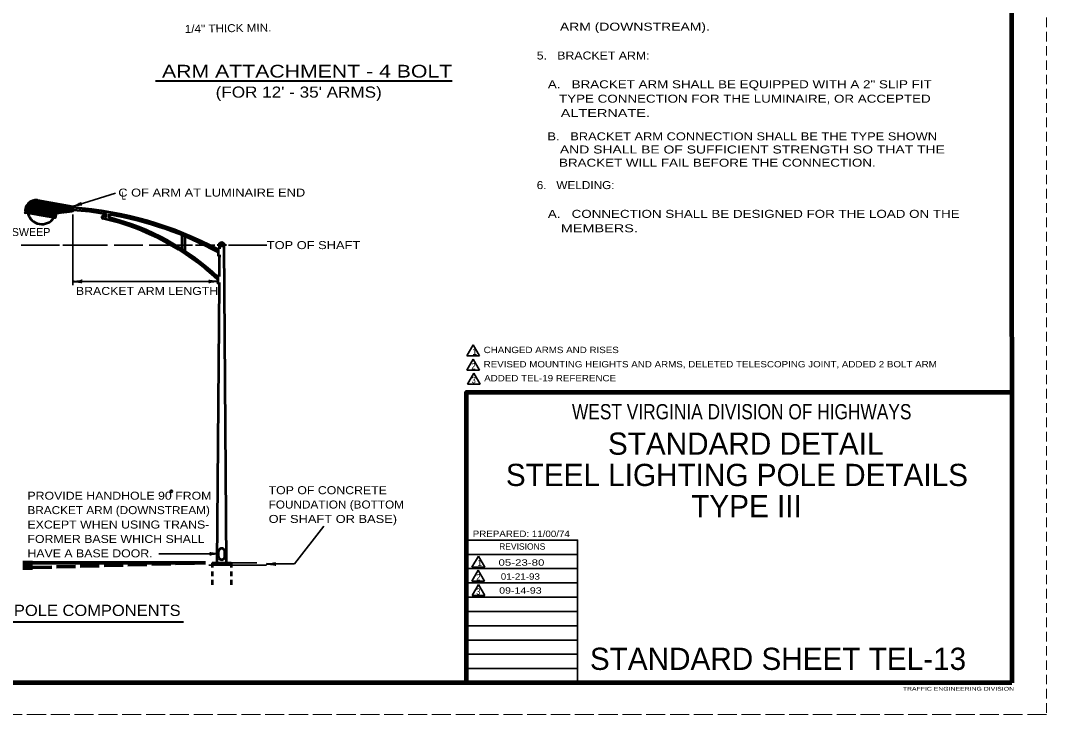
# Model space of a CAD drawing. Extents: x -1 to 679, y -228 to 440.
# Drawn here: x 356 to 679, y 0.2 to 218.8 of the extents above; entities that cross this region are included whole.
import ezdxf
from ezdxf.enums import TextEntityAlignment as Align

# ---------------------------------------------------------------- set-up
doc = ezdxf.new("R2010")
doc.units = 0
doc.header["$PDMODE"] = 32
doc.header["$PDSIZE"] = 0.5
for name, pattern in [('LONG_DASHED', [7.5, 6, -1.5]), ('MEDIUM_DASHED', [4.5, 3, -1.5]), ('SHORT_DASHED', [2.7, 1.5, -1.2])]:
    doc.linetypes.add(name, pattern=pattern)
doc.layers.add('1', color=7, linetype='Continuous', lineweight=35)
doc.layers.add('61', color=7, linetype='Continuous', lineweight=35)

msp = doc.modelspace()

# ---------------------------------------------------------------- linework, layer by layer
at = {"layer": '1', "linetype": 'MEDIUM_DASHED', "lineweight": 13}
msp.add_line((679.041, 440.237), (679.021, 0.217), dxfattribs=at)
at = {"layer": '1', "lineweight": 40}
for p, q in [((398.499, 199.759), (491.884, 199.759)), ((352.69, 29.414), (407.27, 29.414))]:
    msp.add_line(p, q, dxfattribs=at)
at = {"layer": '1', "lineweight": 53}
for p, q in [((357.57, 159.554), (360.171, 162.134)), ((357.611, 159.674), (360.03, 162.094)), ((357.671, 159.834), (359.87, 162.054)), ((357.71, 159.994), (359.71, 161.994)), ((357.791, 160.194), (359.53, 161.914)), ((357.89, 160.394), (359.31, 161.814)), ((358.05, 160.654), (359.05, 161.654)), ((358.09, 159.954), (360.31, 162.154)), ((358.21, 159.954), (360.43, 162.194)), ((358.31, 159.954), (360.55, 162.194)), ((358.411, 159.954), (360.671, 162.214)), ((358.53, 159.954), (360.791, 162.214)), ((358.63, 159.954), (360.89, 162.214)), ((358.731, 159.954), (361.01, 162.214)), ((358.851, 159.954), (361.111, 162.214)), ((358.95, 159.954), (361.21, 162.214)), ((359.05, 159.954), (361.31, 162.214)), ((359.171, 159.954), (361.39, 162.194)), ((359.27, 159.954), (361.49, 162.174)), ((359.37, 159.954), (361.57, 162.154)), ((359.49, 159.954), (361.671, 162.134)), ((359.59, 159.954), (361.77, 162.134)), ((359.69, 159.954), (361.851, 162.114)), ((359.81, 159.954), (361.95, 162.094)), ((359.911, 159.954), (362.03, 162.074)), ((360.01, 159.954), (362.13, 162.054)), ((360.13, 159.954), (362.21, 162.054)), ((360.231, 159.954), (362.31, 162.034)), ((360.351, 159.954), (362.39, 162.014)), ((360.45, 159.954), (362.49, 161.994)), ((360.55, 159.954), (362.57, 161.974)), ((360.671, 159.954), (362.671, 161.974)), ((360.77, 159.954), (362.77, 161.954)), ((360.87, 159.954), (362.851, 161.934)), ((360.99, 159.954), (362.95, 161.914)), ((361.09, 159.954), (363.03, 161.894)), ((361.19, 159.954), (363.13, 161.894)), ((361.31, 159.954), (363.21, 161.874)), ((361.411, 159.954), (363.31, 161.854)), ((361.51, 159.954), (363.39, 161.834)), ((361.63, 159.954), (363.49, 161.814)), ((361.731, 159.954), (363.57, 161.794)), ((361.83, 159.954), (363.671, 161.794)), ((361.95, 159.954), (363.77, 161.774)), ((362.05, 159.954), (363.851, 161.754)), ((362.15, 159.954), (363.95, 161.734)), ((362.27, 159.954), (364.03, 161.714)), ((362.37, 159.954), (364.13, 161.714)), ((362.471, 159.954), (364.21, 161.694)), ((362.59, 159.954), (364.31, 161.674)), ((362.69, 159.954), (364.39, 161.654)), ((362.791, 159.954), (364.49, 161.634)), ((362.911, 159.954), (364.57, 161.634)), ((363.01, 159.954), (364.671, 161.614)), ((363.13, 159.954), (364.77, 161.594)), ((363.231, 159.954), (364.851, 161.574)), ((363.33, 159.954), (364.95, 161.554)), ((363.45, 159.954), (365.03, 161.554)), ((363.55, 159.954), (365.13, 161.534)), ((357.49, 159.034), (358.231, 159.774)), ((357.49, 158.914), (358.33, 159.774)), ((357.49, 158.814), (358.45, 159.774)), ((357.49, 158.714), (358.55, 159.774)), ((357.49, 158.594), (358.65, 159.774)), ((357.49, 158.514), (358.77, 159.774)), ((357.51, 159.154), (358.111, 159.774)), ((357.51, 158.414), (358.87, 159.774)), ((357.51, 158.314), (358.971, 159.774)), ((357.53, 159.274), (358.07, 159.834)), ((357.55, 159.414), (358.07, 159.934)), ((357.57, 158.254), (359.09, 159.774)), ((357.671, 158.234), (359.19, 159.774)), ((357.75, 158.234), (359.291, 159.774)), ((357.851, 158.214), (359.411, 159.774)), ((357.93, 158.194), (359.51, 159.774)), ((358.03, 158.174), (359.611, 159.774)), ((358.111, 158.154), (359.731, 159.774)), ((358.21, 158.154), (359.83, 159.774)), ((358.31, 158.134), (359.93, 159.774)), ((358.39, 158.114), (360.05, 159.774)), ((358.49, 158.094), (360.15, 159.774)), ((358.57, 158.074), (360.25, 159.774)), ((358.671, 158.074), (360.37, 159.774)), ((358.75, 158.054), (360.471, 159.774)), ((358.851, 158.034), (360.57, 159.774)), ((358.93, 158.014), (360.69, 159.774)), ((359.03, 157.994), (360.791, 159.774)), ((359.111, 157.994), (360.89, 159.774)), ((359.21, 157.974), (361.01, 159.774)), ((359.291, 157.954), (361.111, 159.774)), ((359.39, 157.934), (361.231, 159.774)), ((359.49, 157.914), (361.33, 159.774)), ((359.57, 157.914), (361.43, 159.774)), ((359.671, 157.894), (361.55, 159.774)), ((359.75, 157.874), (361.65, 159.774)), ((359.851, 157.854), (361.75, 159.774)), ((359.93, 157.834), (361.87, 159.774)), ((360.03, 157.834), (361.971, 159.774)), ((360.111, 157.814), (362.07, 159.774)), ((360.21, 157.794), (362.19, 159.774)), ((360.291, 157.774), (362.291, 159.774)), ((360.39, 157.754), (362.39, 159.774)), ((360.49, 157.754), (362.51, 159.774)), ((360.57, 157.734), (362.611, 159.774)), ((360.671, 157.714), (362.71, 159.774)), ((360.75, 157.694), (362.83, 159.774)), ((360.851, 157.674), (362.93, 159.774)), ((360.93, 157.674), (363.03, 159.774)), ((361.03, 157.654), (363.15, 159.774)), ((361.111, 157.634), (363.25, 159.774)), ((361.21, 157.614), (363.351, 159.774)), ((361.291, 157.594), (363.471, 159.774)), ((361.39, 157.574), (363.57, 159.774)), ((361.49, 157.574), (363.671, 159.774)), ((361.57, 157.554), (363.791, 159.774)), ((361.671, 157.534), (363.89, 159.774)), ((361.75, 157.514), (364.01, 159.774)), ((361.851, 157.494), (364.111, 159.774)), ((361.93, 157.494), (364.21, 159.774)), ((362.03, 157.474), (364.33, 159.774)), ((362.111, 157.454), (364.43, 159.774)), ((362.21, 157.434), (364.53, 159.774)), ((362.291, 157.414), (364.65, 159.774)), ((362.39, 157.414), (364.75, 159.774)), ((362.49, 157.394), (364.851, 159.774)), ((362.57, 157.374), (364.971, 159.774)), ((362.671, 157.354), (365.07, 159.774)), ((362.75, 157.334), (365.171, 159.774)), ((362.851, 157.334), (365.291, 159.774)), ((362.93, 157.314), (365.39, 159.774)), ((363.03, 157.294), (365.49, 159.774)), ((363.111, 157.274), (365.611, 159.774)), ((363.21, 157.254), (365.71, 159.774)), ((363.291, 157.254), (365.81, 159.774)), ((363.39, 157.234), (365.93, 159.774)), ((363.49, 157.214), (366.03, 159.774)), ((363.57, 157.194), (366.13, 159.774)), ((363.65, 159.954), (365.21, 161.514)), ((363.671, 157.174), (366.25, 159.774)), ((363.75, 157.174), (366.351, 159.774)), ((363.77, 159.954), (365.31, 161.494)), ((363.851, 157.154), (366.45, 159.774)), ((363.87, 159.954), (365.39, 161.474)), ((363.93, 157.134), (366.57, 159.774)), ((363.971, 159.954), (365.49, 161.474)), ((364.03, 157.114), (366.671, 159.774)), ((364.09, 159.954), (365.57, 161.454)), ((364.111, 157.094), (366.791, 159.774)), ((364.19, 159.954), (365.671, 161.434)), ((364.21, 157.094), (366.89, 159.774)), ((364.291, 159.954), (365.77, 161.414)), ((364.291, 157.074), (366.99, 159.774)), ((364.39, 157.054), (367.111, 159.774)), ((364.411, 159.954), (365.851, 161.394)), ((364.49, 157.034), (367.21, 159.774)), ((364.51, 159.954), (365.95, 161.394)), ((364.57, 157.014), (367.31, 159.774)), ((364.611, 159.954), (366.03, 161.374)), ((364.671, 157.014), (367.43, 159.774)), ((364.731, 159.954), (366.13, 161.354)), ((364.75, 156.994), (367.53, 159.774)), ((364.83, 159.954), (366.21, 161.334)), ((364.851, 156.974), (367.63, 159.774)), ((364.93, 159.954), (366.31, 161.314)), ((364.93, 156.954), (367.75, 159.774)), ((365.03, 156.934), (367.851, 159.774)), ((365.05, 159.954), (366.39, 161.314)), ((365.111, 156.934), (367.95, 159.774)), ((365.15, 159.954), (366.49, 161.294)), ((365.21, 156.914), (368.07, 159.774)), ((365.25, 159.954), (366.57, 161.274)), ((365.291, 156.894), (368.171, 159.774)), ((365.37, 159.954), (366.671, 161.254)), ((365.39, 156.874), (368.27, 159.774)), ((365.471, 159.954), (366.77, 161.234)), ((365.49, 156.854), (368.39, 159.774)), ((365.57, 159.954), (366.851, 161.234)), ((365.57, 156.854), (368.49, 159.774)), ((365.671, 156.834), (368.59, 159.774)), ((365.69, 159.954), (366.95, 161.214)), ((365.75, 156.814), (368.71, 159.774)), ((365.791, 159.954), (367.03, 161.194)), ((365.851, 156.794), (368.81, 159.774)), ((365.89, 159.954), (367.13, 161.174)), ((366.01, 159.954), (367.21, 161.154)), ((366.111, 159.954), (367.31, 161.154)), ((366.231, 159.954), (367.39, 161.134)), ((366.33, 159.954), (367.49, 161.114)), ((366.43, 159.954), (367.57, 161.094)), ((366.55, 159.954), (367.671, 161.074)), ((366.65, 159.954), (367.75, 161.074)), ((366.75, 159.954), (367.851, 161.054)), ((366.87, 159.954), (367.95, 161.034)), ((366.971, 159.954), (368.03, 161.014)), ((367.07, 159.954), (368.13, 160.994)), ((367.19, 159.954), (368.21, 160.994)), ((367.231, 158.094), (368.911, 159.774)), ((367.291, 159.954), (368.31, 160.974)), ((367.37, 158.094), (369.03, 159.774)), ((367.39, 159.954), (368.39, 160.954)), ((367.49, 158.114), (369.13, 159.774)), ((367.51, 159.954), (368.49, 160.934)), ((367.611, 159.954), (368.57, 160.914)), ((367.611, 158.134), (369.231, 159.774)), ((367.71, 159.954), (368.671, 160.914)), ((367.731, 158.154), (369.351, 159.774)), ((367.83, 159.954), (368.75, 160.894)), ((367.851, 158.154), (369.45, 159.774)), ((367.93, 159.954), (368.851, 160.874)), ((367.971, 158.174), (369.55, 159.774)), ((368.03, 159.954), (368.95, 160.854)), ((368.09, 158.194), (369.671, 159.774)), ((368.15, 159.954), (369.03, 160.834)), ((368.21, 158.214), (369.77, 159.774)), ((368.25, 159.954), (369.13, 160.834)), ((368.33, 158.214), (369.89, 159.774)), ((368.351, 159.954), (369.21, 160.814)), ((368.45, 158.234), (369.99, 159.774)), ((368.471, 159.954), (369.31, 160.794)), ((368.57, 159.954), (369.39, 160.774)), ((368.57, 158.254), (370.09, 159.774)), ((368.671, 159.954), (369.49, 160.754)), ((368.71, 158.274), (370.21, 159.774)), ((368.791, 159.954), (369.57, 160.754)), ((368.83, 158.274), (370.31, 159.774)), ((368.89, 159.954), (369.671, 160.734)), ((368.95, 158.294), (370.411, 159.774)), ((369.01, 159.954), (369.75, 160.714)), ((369.07, 158.314), (370.53, 159.774)), ((369.111, 159.954), (369.851, 160.694)), ((369.19, 158.334), (370.63, 159.774)), ((369.21, 159.954), (369.95, 160.674)), ((369.31, 158.334), (370.731, 159.774)), ((369.33, 159.954), (370.03, 160.674)), ((369.43, 159.954), (370.13, 160.654)), ((369.43, 158.354), (370.851, 159.774)), ((369.53, 159.954), (370.21, 160.634)), ((369.55, 158.374), (370.95, 159.774)), ((369.65, 159.954), (370.31, 160.614)), ((369.671, 158.394), (371.05, 159.774)), ((369.75, 159.954), (370.39, 160.594)), ((369.791, 158.394), (371.171, 159.774)), ((369.851, 159.954), (370.49, 160.594)), ((369.911, 158.414), (371.27, 159.774)), ((369.971, 159.954), (370.57, 160.574)), ((370.05, 158.434), (371.37, 159.774)), ((370.07, 159.954), (370.671, 160.554)), ((370.171, 159.954), (370.75, 160.534)), ((370.171, 158.454), (371.49, 159.774)), ((370.291, 159.954), (370.851, 160.514)), ((370.291, 158.454), (371.59, 159.774)), ((370.39, 159.954), (370.95, 160.514)), ((370.411, 158.474), (371.69, 159.774)), ((370.49, 159.954), (371.03, 160.494)), ((370.53, 158.494), (371.81, 159.774)), ((370.611, 159.954), (371.13, 160.474)), ((370.65, 158.514), (371.911, 159.774)), ((370.71, 159.954), (371.21, 160.454)), ((370.77, 158.514), (372.01, 159.774)), ((370.81, 159.954), (371.31, 160.434)), ((370.89, 158.534), (372.45, 160.094)), ((370.93, 159.954), (371.39, 160.434)), ((371.01, 158.554), (372.45, 159.994)), ((371.03, 159.954), (371.49, 160.414)), ((371.13, 159.954), (371.57, 160.394)), ((371.13, 158.574), (372.45, 159.874)), ((371.25, 159.954), (371.671, 160.374)), ((371.27, 158.574), (372.45, 159.774)), ((371.351, 159.954), (371.75, 160.354)), ((371.39, 158.594), (372.45, 159.674)), ((371.45, 159.954), (371.851, 160.354)), ((371.51, 158.614), (372.45, 159.554)), ((371.57, 159.954), (371.95, 160.334)), ((371.63, 158.634), (372.45, 159.454)), ((371.671, 159.954), (372.03, 160.314)), ((371.75, 158.634), (372.45, 159.354)), ((371.791, 159.954), (372.13, 160.294)), ((371.87, 158.654), (372.45, 159.234)), ((371.89, 159.954), (372.21, 160.274)), ((371.99, 159.954), (372.31, 160.274)), ((371.99, 158.674), (372.45, 159.134)), ((372.07, 159.934), (372.39, 160.254)), ((372.07, 159.834), (372.45, 160.194)), ((372.111, 158.694), (372.45, 159.034)), ((372.231, 158.694), (372.45, 158.914)), ((372.351, 158.714), (372.45, 158.814)), ((365.93, 156.774), (367.19, 158.034)), ((366.03, 156.774), (367.171, 157.894)), ((366.111, 156.754), (367.13, 157.754)), ((366.21, 156.734), (367.09, 157.634)), ((366.291, 156.714), (367.07, 157.494)), ((366.39, 156.694), (367.03, 157.354)), ((366.471, 156.694), (367.01, 157.214)), ((366.57, 156.674), (366.971, 157.074)), ((366.671, 156.654), (366.93, 156.934)), ((366.75, 156.634), (366.911, 156.794)), ((366.851, 156.614), (366.87, 156.654)), ((383.03, 156.754), (383.03, 158.034)), ((383.99, 156.514), (383.99, 157.874)), ((406.851, 146.714), (406.851, 151.174)), ((407.791, 146.114), (407.791, 150.774)), ((418.19, 148.334), (420.47, 148.334)), ((418.19, 148.334), (418.19, 147.774)), ((418.19, 147.774), (420.47, 147.774)), ((419.07, 147.194), (418.19, 147.194)), ((418.19, 147.194), (418.19, 144.554)), ((418.57, 147.774), (418.57, 147.194)), ((420.83, 47.974), (420.09, 147.774)), ((420.47, 148.334), (420.47, 147.774)), ((419.07, 144.554), (418.19, 144.554)), ((418.55, 144.554), (418.51, 138.494)), ((418.49, 135.854), (417.81, 47.974)), ((419.01, 138.494), (418.13, 138.494)), ((418.13, 138.494), (418.13, 135.854)), ((419.01, 135.854), (418.13, 135.854)), ((418.33, 49.994), (418.33, 51.494)), ((420.33, 49.994), (420.33, 51.494)), ((416.31, 47.974), (422.351, 47.974))]:
    msp.add_line(p, q, dxfattribs=at)
at = {"layer": '1'}
for p, q in [((372.45, 160.234), (385.87, 164.374)), ((372.45, 157.714), (372.45, 135.394)), ((368.291, 148.054), (356.21, 148.054)), ((383.411, 148.054), (369.31, 148.054)), ((394.51, 148.054), (385.43, 148.054)), ((410.13, 148.054), (396.53, 148.054)), ((411.13, 148.054), (417.19, 148.054)), ((433.57, 148.054), (421.47, 148.054)), ((418.13, 136.594), (372.45, 136.594)), ((498.561, 116.622), (496.561, 113.158)), ((498.561, 116.622), (500.561, 113.158)), ((500.561, 113.158), (496.561, 113.158)), ((498.561, 112.12), (496.561, 108.656)), ((498.561, 112.12), (500.561, 108.656)), ((500.561, 108.656), (496.561, 108.656)), ((498.729, 107.726), (496.729, 104.261)), ((498.729, 107.726), (500.729, 104.261)), ((500.729, 104.261), (496.729, 104.261)), ((451.49, 59.514), (442.231, 47.614)), ((418.39, 50.814), (399.55, 50.814)), ((531.421, 50.637), (496.441, 50.637)), ((500.149, 50.111), (498.149, 46.647)), ((415.291, 47.214), (433.43, 47.214)), ((422.351, 47.974), (430.411, 47.974)), ((433.43, 47.614), (442.231, 47.614)), ((531.421, 46.137), (496.441, 46.137)), ((500.114, 45.642), (498.114, 42.178)), ((500.114, 45.642), (502.114, 42.178)), ((502.114, 42.178), (498.114, 42.178)), ((531.421, 41.637), (496.441, 41.637)), ((500.2, 41.118), (498.2, 37.654)), ((500.2, 41.118), (502.2, 37.654)), ((531.421, 37.117), (496.441, 37.117)), ((502.2, 37.654), (498.2, 37.654)), ((531.421, 32.637), (496.441, 32.637)), ((531.421, 28.157), (496.441, 28.157)), ((531.421, 23.657), (496.441, 23.657)), ((531.421, 19.157), (496.441, 19.157)), ((531.421, 14.637), (496.441, 14.637))]:
    msp.add_line(p, q, dxfattribs=at)
at = {"layer": '1', "lineweight": 106}
for p, q in [((356.77, 47.974), (359.81, 47.974)), ((356.77, 46.454), (359.81, 46.454))]:
    msp.add_line(p, q, dxfattribs=at)
at = {"layer": '1', "lineweight": 70}
msp.add_line((359.81, 47.974), (414.231, 47.974), dxfattribs=at)
at = {"layer": '1', "linetype": 'LONG_DASHED', "lineweight": 70}
msp.add_line((359.81, 46.454), (414.231, 47.974), dxfattribs=at)
at = {"layer": '1', "linetype": 'SHORT_DASHED', "lineweight": 53}
for p, q in [((416.31, 47.974), (416.31, 39.914)), ((422.351, 47.974), (422.351, 39.914))]:
    msp.add_line(p, q, dxfattribs=at)
at = {"layer": '1', "lineweight": 53}
msp.add_lwpolyline([(361.291, 162.214), (372.45, 160.234), (372.45, 158.734), (367.21, 158.074), (366.87, 156.614), (357.53, 158.274)], dxfattribs=at)
msp.add_lwpolyline([(358.07, 159.954), (372.07, 159.954), (372.07, 159.774), (358.07, 159.774)], close=True, dxfattribs=at)
at = {"layer": '1', "lineweight": 158}
msp.add_lwpolyline([(496.421, 10.197), (496.421, 101.777), (668.081, 101.777)], dxfattribs=at)
at = {"layer": '1'}
for points in [[(531.421, 10.157), (531.421, 55.117), (496.441, 55.117)], [(500.149, 50.111), (502.149, 46.647), (498.149, 46.647)]]:
    msp.add_lwpolyline(points, dxfattribs=at)
msp.add_circle((403.483, 70.491), 0.325, dxfattribs=at)
at = {"layer": '1', "lineweight": 53}
for centre, radius, start, end in [((360.941, 158.77), 3.456, 84.23953, 188.38162), ((364.26, 45.866), 114.289, 61.84402, 85.88743), ((364.26, 45.11), 114.289, 80.54208, 85.88743), ((362.702, 159.236), 4.57, 193.94762, 326.05059), ((381.968, 156.837), 0.383, 99.37484, 260.62516), ((382.081, 157.086), 0.651, 235.53017, 254.38288), ((364.379, 80.626), 78.568, 76.2603, 77.11012), ((364.379, 79.87), 78.568, 46.83897, 77.11012), ((364.26, 45.11), 114.289, 61.84402, 80.06146), ((364.379, 80.626), 78.568, 46.83897, 75.54976), ((419.328, 148.052), 0.802, 20.3922, 159.6078), ((419.328, 51.521), 0.993, 358.58875, 181.41125), ((419.328, 49.949), 0.993, 178.58875, 1.41125)]:
    msp.add_arc(centre, radius, start, end, dxfattribs=at)
at = {"layer": '1', "lineweight": 40}
for centre, major_axis, ratio, start_param, end_param in [((373.425, 160.829), (-1.674, -0.68), 0.122415, 0.8963533, 3.1415927), ((373.598, 160.367), (1.744, 0.352), 0.07063, 6.2823074, 8.5597026), ((373.585, 136.385), (-1.77, 0.177), 0.07063, 3.1407148, 5.41811), ((373.585, 136.385), (-1.77, 0.177), 0.07063, 3.1407148, 5.41811), ((373.556, 136.876), (-1.8, -0.157), 0.122415, 0.8963533, 3.1415927), ((373.556, 136.876), (-1.8, -0.157), 0.122415, 0.8963533, 3.1415927), ((417.024, 136.319), (1.8, 0.157), 0.122415, 0.8963533, 3.1415927), ((417.024, 136.319), (1.8, 0.157), 0.122415, 0.8963533, 3.1415927), ((416.994, 136.811), (1.77, -0.177), 0.07063, 3.1407148, 5.41811), ((416.994, 136.811), (1.77, -0.177), 0.07063, 3.1407148, 5.41811), ((417.298, 50.538), (1.8, 0.157), 0.122415, 0.8963533, 3.1415927), ((417.268, 51.03), (1.77, -0.177), 0.07063, 3.1407148, 5.41811), ((434.565, 47.396), (-1.77, 0.177), 0.07063, 3.1407148, 5.41811), ((434.536, 47.888), (-1.8, -0.157), 0.122415, 0.8963533, 3.1415927)]:
    msp.add_ellipse(centre, major_axis=major_axis, ratio=ratio, start_param=start_param, end_param=end_param, dxfattribs=at)
at = {"layer": '1'}
for p in [(357.53, 158.274), (358.53, 161.234)]:
    msp.add_point(p, dxfattribs=at)
at = {"layer": '61', "lineweight": 158}
for p, q in [((668.061, 430.237), (668.081, 10.197)), ((668.081, 10.197), (29.021, 10.217))]:
    msp.add_line(p, q, dxfattribs=at)
at = {"layer": '61', "linetype": 'LONG_DASHED', "lineweight": 13}
msp.add_line((679.021, 0.217), (-1.039, 0.197), dxfattribs=at)

# ---------------------------------------------------------------- texts
at = {"layer": '1', "width": 1.1}
msp.add_text('1/4" THICK MIN.', height=2.5, rotation=1, dxfattribs=at).set_placement((407.73, 214.882))
at = {"layer": '1'}
for s, height, width, p in [('      ARM (DOWNSTREAM).', 2.52, 1.3, (518.531, 215.597)), ('5.   BRACKET ARM:', 2.52, 1.15, (518.531, 206.517)), ('ARM ATTACHMENT - 4 BOLT', 4, 1.25, (400.54, 200.841)), ("(FOR 12' - 35' ARMS)", 3.5, 1.15, (417.436, 194.502)), ('   A.   BRACKET ARM SHALL BE EQUIPPED WITH A 2" SLIP FIT', 2.52, 1.25, (518.531, 197.457)), ('      TYPE CONNECTION FOR THE LUMINAIRE, OR ACCEPTED', 2.52, 1.25, (518.531, 192.917)), ('      ALTERNATE.', 2.52, 1.35, (518.531, 188.397)), ('   B.   BRACKET ARM CONNECTION SHALL BE THE TYPE SHOWN', 2.52, 1.2, (518.531, 181.05)), ('      AND SHALL BE OF SUFFICIENT STRENGTH SO THAT THE', 2.52, 1.3, (518.531, 176.91)), ('      BRACKET WILL FAIL BEFORE THE CONNECTION.', 2.52, 1.25, (518.531, 172.75)), ('6.   WELDING:', 2.52, 1.1, (518.531, 165.697)), ('C OF ARM AT LUMINAIRE END', 2.52, 1.2, (386.77, 163.334)), ('L', 2.52, 0.75, (387.791, 162.414)), ('   A.   CONNECTION SHALL BE DESIGNED FOR THE LOAD ON THE', 2.52, 1.25, (518.531, 156.637)), ('      MEMBERS. ', 2.52, 1.35, (518.531, 152.097)), ('TOP OF SHAFT', 2.52, 1.2, (433.53, 146.794)), ('BRACKET ARM LENGTH', 2.52, 1.15, (373.45, 132.354)), ('CHANGED ARMS AND RISES', 2, 1.15, (501.818, 114.032)), ('2', 2, 0.9, (497.939, 108.908)), ('REVISED MOUNTING HEIGHTS AND ARMS, DELETED TELESCOPING JOINT, ADDED 2 BOLT ARM', 2, 1.15, (501.818, 109.53)), ('ADDED TEL-19 REFERENCE', 2, 1.15, (501.986, 105.135)), ('3', 2, 0.9, (498.004, 104.545)), ('TOP OF CONCRETE', 2.52, 1.15, (434.111, 69.594)), ('PROVIDE HANDHOLE 90 FROM', 2.52, 1.15, (358.171, 67.854)), ('BRACKET ARM (DOWNSTREAM)', 2.52, 1.1, (358.171, 63.314)), ('FOUNDATION (BOTTOM', 2.52, 1.1, (434.111, 65.074)), ('OF SHAFT OR BASE)', 2.52, 1.2, (434.111, 60.534)), ('EXCEPT WHEN USING TRANS-', 2.52, 1.15, (358.171, 58.774)), ('PREPARED: 11/00/74', 1.998, 1.15, (498.381, 56.117)), ('FORMER BASE WHICH SHALL', 2.52, 1.15, (358.171, 54.234)), ('HAVE A BASE DOOR.', 2.52, 1.15, (358.171, 49.694)), ('2', 2, 0.9, (499.488, 42.438)), ('3', 2, 0.9, (499.475, 37.938)), ('POLE COMPONENTS', 3.528, 1.1, (353.911, 31.234)), ('TRAFFIC ENGINEERING DIVISION', 1.2, 1.35, (633.801, 7.697))]:
    msp.add_text(s, height=height, dxfattribs=dict(at, width=width)).set_placement(p)
for s, height, p in [('UPSWEEP', 2.52, (348.55, 150.914)), ('1', 2, (498.249, 113.487)), ('REVISIONS', 1.998, (506.701, 52.117)), ('1', 2, (499.837, 46.976)), ('STANDARD SHEET TEL-13', 6.993, (535.261, 14.237))]:
    msp.add_text(s, height=height, dxfattribs=at).set_placement(p)
for s, height, width, p in [('WEST VIRGINIA DIVISION OF HIGHWAYS', 4.795, 0.85, (583.07, 93.177)), ('05-23-80', 2, 1.35, (513.721, 47.057)), ('01-21-93', 2, 1.15, (513.37, 42.657)), ('09-14-93', 2, 1.25, (513.391, 38.257))]:
    msp.add_text(s, height=height, dxfattribs=dict(at, width=width)).set_placement(p, align=Align.CENTER)
for s, p in [('STANDARD DETAIL', (584.338, 82.017)), ('STEEL LIGHTING POLE DETAILS', (581.565, 72.167)), ('TYPE III', (584.595, 62.317))]:
    msp.add_text(s, height=6.993, dxfattribs=at).set_placement(p, align=Align.CENTER)

doc.saveas('drawing.dxf')
